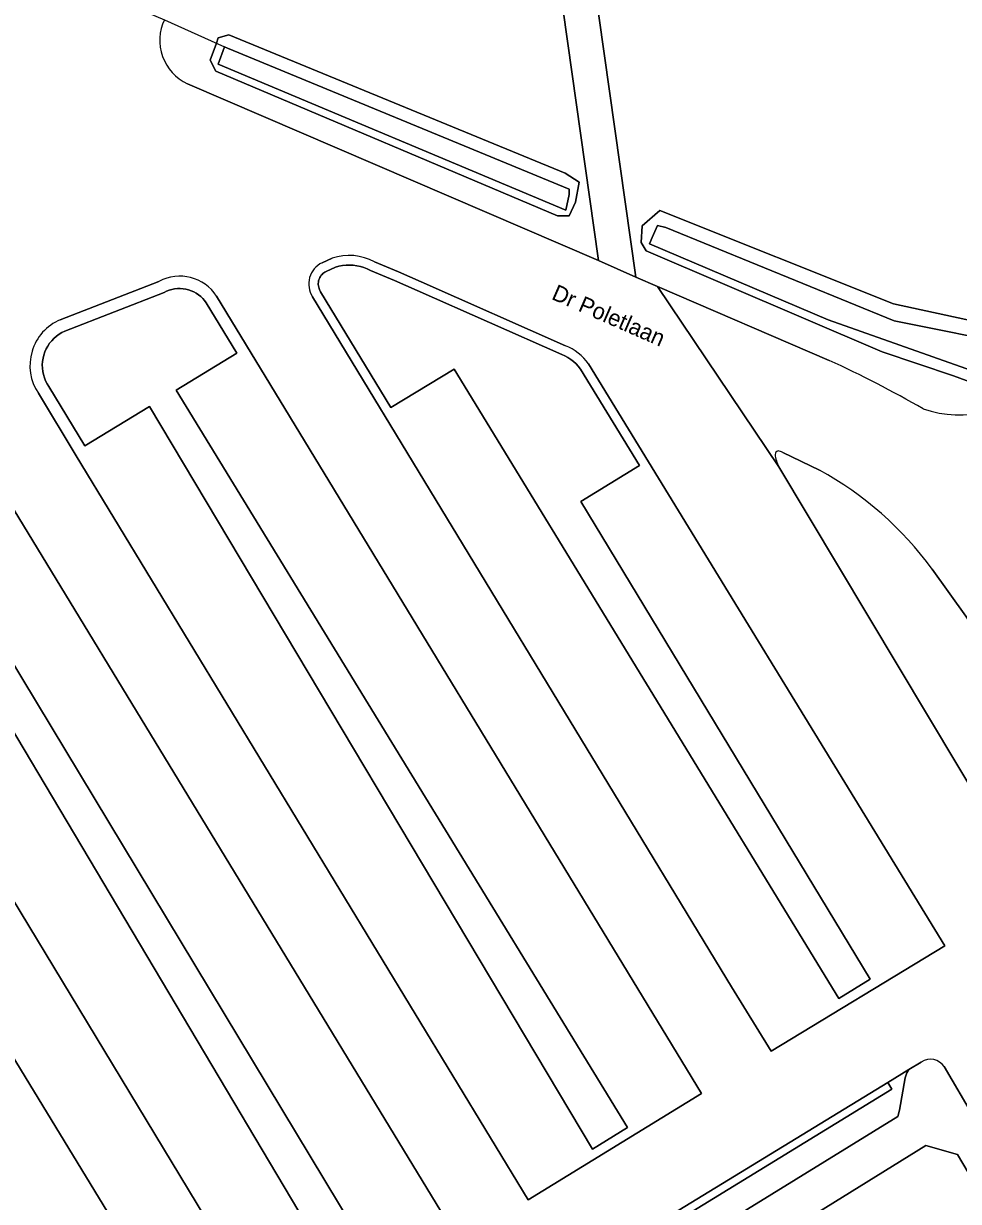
# Model space of a CAD drawing. Extents: x 158132 to 159664, y 385256 to 387218.
# Drawn here: x 158617.8 to 158675.2, y 386803.8 to 386876.1 of the extents above; entities that cross this region are included whole.
import ezdxf

# ---------------------------------------------------------------- set-up
doc = ezdxf.new("R2010")
doc.units = 0
for name, color, linetype in [('IMGEO_Duiker', 7, 'Continuous'), ('IMGEO_Gemengd_bos', 7, 'Continuous'), ('IMGEO_Groenvoorziening', 7, 'Continuous'), ('IMGEO_Oever', 7, 'Continuous'), ('IMGEO_Openbare_ruimte_label', 7, 'Continuous'), ('IMGEO_Parkeervlak_open', 7, 'Continuous'), ('IMGEO_Rijbaan_lokaal_gesloten', 7, 'Continuous'), ('IMGEO_Rijbaan_lokaal_open', 7, 'Continuous'), ('IMGEO_Voetpad_gesloten', 7, 'Continuous'), ('IMGEO_Voetpad_open', 7, 'Continuous'), ('IMGEO_Waterloop', 7, 'Continuous')]:
    doc.layers.add(name, color=color, linetype=linetype)

msp = doc.modelspace()

# ---------------------------------------------------------------- linework, layer by layer
at = {"layer": 'IMGEO_Duiker'}
msp.add_lwpolyline([(158619.115, 386879.444), (158619.244, 386879.388), (158620.829, 386878.697), (158626.462, 386876.298), (158630.151, 386874.635), (158630.327, 386874.558)], dxfattribs=at)
at = {"layer": 'IMGEO_Gemengd_bos'}
msp.add_lwpolyline([(158687.811, 387060.409), (158689.817, 387061.157), (158703.822, 387101.712), (158681.036, 387088.113), (158663.513, 387076.566), (158660.407, 387074.962), (158660.01, 387075.699), (158644.038, 387067.333), (158614.63, 387050.481), (158601.872, 387043.698), (158647.808, 386955.65), (158659.443, 386961.72), (158679.256, 386924.451), (158648.608, 386908.461), (158655.384, 386860.517), (158656.73, 386859.937), (158667.25, 386855.404)], dxfattribs=at)
msp.add_lwpolyline([(158656.867, 386864.6), (158671.198, 386858.872), (158680.086, 386856.956), (158679.662, 386854.103), (158679.075, 386853.884), (158677.759, 386853.393), (158674.889, 386854.448), (158670.513, 386855.935), (158656.017, 386862.127), (158655.715, 386862.635), (158655.771, 386863.651)], close=True, dxfattribs=at)
for centre, radius, start, end in [((158638.753, 386793.042), 68.565, 60.00896, 65.44143), ((158675.246, 386859.022), 6.959, 251.40123, 316.75632)]:
    msp.add_arc(centre, radius, start, end, dxfattribs=at)
at = {"layer": 'IMGEO_Groenvoorziening'}
for points in [[(158627.875, 386872.369), (158630.221, 386871.36), (158653.095, 386861.525), (158646.576, 386907.685)], [(158666.67, 386848.674), (158664.408, 386849.76)], [(158664.173, 386848.883), (158678.814, 386824.435)], [(158639.846, 386799.251), (158611.508, 386846.181)], [(158681.302, 386830.498), (158677.109, 386837.457), (158675.65, 386839.708), (158673.58, 386842.598)], [(158612.053, 386841.27), (158637.792, 386798.011)], [(158679.268, 386799.741), (158675.134, 386806.696), (158673.193, 386807.258), (158661.926, 386800.289), (158662.412, 386799.415), (158661.038, 386798.599), (158660.541, 386799.433), (158660.438, 386799.369), (158658.36, 386798.138), (158645.464, 386790.273), (158643.388, 386789.021), (158630.554, 386781.129), (158628.471, 386779.831), (158615.58, 386772.037), (158613.511, 386770.8), (158602.495, 386764.073), (158600.165, 386764.485), (158598.81, 386764.724), (158595.398, 386758.151), (158598.248, 386753.226), (158595.064, 386751.272), (158577.065, 386740.009)]]:
    msp.add_lwpolyline(points, dxfattribs=at)
for points in [[(158651.055, 386866.893), (158651.904, 386866.336), (158651.692, 386865.112), (158651.303, 386864.276), (158650.589, 386864.276), (158629.61, 386873.148), (158629.277, 386873.812), (158629.654, 386874.859), (158629.769, 386875.176), (158630.416, 386875.365)], [(158655.619, 386848.952), (158651.99, 386854.875), (158651.861, 386855.04), (158651.719, 386855.194), (158651.564, 386855.335), (158651.399, 386855.464), (158651.223, 386855.579), (158651.039, 386855.679), (158650.847, 386855.764), (158641.978, 386859.686), (158640.591, 386860.3), (158639.1, 386860.91), (158638.904, 386861.011), (158638.699, 386861.095), (158638.488, 386861.162), (158638.272, 386861.21), (158638.053, 386861.241), (158637.832, 386861.253), (158637.611, 386861.246), (158637.392, 386861.221), (158637.175, 386861.178), (158636.962, 386861.117), (158636.381, 386860.861), (158636.314, 386860.824), (158636.251, 386860.781), (158636.192, 386860.732), (158636.137, 386860.678), (158636.087, 386860.62), (158636.043, 386860.557), (158636.005, 386860.491), (158635.972, 386860.422), (158635.946, 386860.35), (158635.926, 386860.276), (158635.913, 386860.201), (158635.907, 386860.124), (158635.907, 386860.048), (158635.914, 386859.971), (158635.928, 386859.896), (158635.949, 386859.822), (158635.976, 386859.751), (158636.009, 386859.682), (158636.049, 386859.616), (158640.363, 386852.514), (158644.245, 386854.872), (158667.842, 386816.275), (158669.778, 386817.448), (158652.015, 386846.744)], [(158654.874, 386808.351), (158627.174, 386853.568), (158630.909, 386855.841), (158629.026, 386858.935), (158628.925, 386859.074), (158628.813, 386859.204), (158628.689, 386859.323), (158628.555, 386859.431), (158628.413, 386859.527), (158628.262, 386859.609), (158628.105, 386859.679), (158627.942, 386859.734), (158627.775, 386859.774), (158627.605, 386859.8), (158627.434, 386859.811), (158627.262, 386859.806), (158627.091, 386859.786), (158626.923, 386859.752), (158626.759, 386859.702), (158626.599, 386859.639), (158626.446, 386859.561), (158620.361, 386857.198), (158620.178, 386857.11), (158620.004, 386857.007), (158619.84, 386856.888), (158619.687, 386856.756), (158619.546, 386856.61), (158619.418, 386856.453), (158619.305, 386856.285), (158619.208, 386856.107), (158619.126, 386855.922), (158619.061, 386855.73), (158619.013, 386855.534), (158618.982, 386855.333), (158618.97, 386855.131), (158618.975, 386854.929), (158618.998, 386854.728), (158619.039, 386854.529), (158619.097, 386854.335), (158619.172, 386854.147), (158619.264, 386853.967), (158619.371, 386853.795), (158621.577, 386850.166), (158625.552, 386852.581), (158652.735, 386807.04)], [(158672.143, 386811.908), (158670.853, 386811.121), (158671.1, 386810.713), (158658.248, 386802.847), (158656.171, 386801.575), (158643.345, 386793.726), (158641.261, 386792.449), (158628.427, 386784.594), (158626.326, 386783.308), (158613.495, 386775.456), (158611.401, 386774.174), (158600.138, 386767.28), (158600.031, 386767.075), (158602.159, 386766.707), (158631.575, 386784.467), (158671.459, 386809.025), (158671.568, 386809.413), (158671.926, 386811.406), (158672.029, 386811.721)]]:
    msp.add_lwpolyline(points, close=True, dxfattribs=at)
for centre, radius, start, end in [((158629.124, 386875.037), 2.945, 154.6443, 244.91627), ((158664.173, 386849.627), 0.235, 104.46981, 177.44194), ((158663.805, 386848.379), 1.507, 66.39008, 78.14887), ((158665.708, 386849.775), 1.775, 184.46014, 210.16136), ((158656.337, 386829.956), 21.381, 36.24859, 61.10073)]:
    msp.add_arc(centre, radius, start, end, dxfattribs=at)
at = {"layer": 'IMGEO_Oever'}
for points in [[(158651.055, 386866.893), (158630.416, 386875.365), (158629.769, 386875.176), (158629.654, 386874.859), (158629.277, 386873.812), (158629.61, 386873.148), (158650.589, 386864.276), (158651.303, 386864.276), (158651.692, 386865.112), (158651.904, 386866.336)], [(158630.151, 386874.635), (158630.327, 386874.558), (158651.303, 386865.909), (158651.303, 386865.576), (158651.096, 386864.608), (158629.766, 386873.576)], [(158656.867, 386864.6), (158655.771, 386863.651), (158655.715, 386862.635), (158656.017, 386862.127), (158670.513, 386855.935), (158674.889, 386854.448), (158677.759, 386853.393), (158679.075, 386853.884), (158679.662, 386854.103), (158680.086, 386856.956), (158671.198, 386858.872)], [(158657.221, 386863.55), (158671.234, 386857.838), (158678.998, 386856.266), (158678.998, 386854.77), (158678.671, 386854.535), (158678.008, 386854.06), (158667.187, 386857.887), (158656.239, 386862.56), (158656.397, 386862.932), (158656.715, 386863.682)]]:
    msp.add_lwpolyline(points, close=True, dxfattribs=at)
at = {"layer": 'IMGEO_Parkeervlak_open'}
for points in [[(158636.75, 386861.663), (158636.133, 386861.392)], [(158651.073, 386856.304), (158642.215, 386860.222), (158640.82, 386860.839), (158639.355, 386861.439)], [(158626.125, 386860.251), (158620.075, 386857.901)], [(158618.732, 386853.384), (158621.057, 386849.56), (158648.785, 386803.923), (158659.417, 386810.444), (158629.668, 386859.34)], [(158635.553, 386859.304), (158661.265, 386816.98), (158663.691, 386813.049), (158674.348, 386819.505), (158652.479, 386855.198)], [(158606.261, 386840.323), (158631.543, 386798.594), (158633.83, 386794.789), (158644.565, 386801.344), (158615.215, 386849.516)], [(158611.508, 386846.181), (158639.846, 386799.251)], [(158637.792, 386798.011), (158612.053, 386841.27)], [(158596.366, 386822.775), (158600.816, 386815.432), (158618.919, 386785.65), (158629.653, 386792.202), (158606.165, 386830.714)]]:
    msp.add_lwpolyline(points, dxfattribs=at)
for points in [[(158655.619, 386848.952), (158652.015, 386846.744), (158669.778, 386817.448), (158667.842, 386816.275), (158644.245, 386854.872), (158640.363, 386852.514), (158636.049, 386859.616), (158636.009, 386859.682), (158635.976, 386859.751), (158635.949, 386859.822), (158635.928, 386859.896), (158635.914, 386859.971), (158635.907, 386860.048), (158635.907, 386860.124), (158635.913, 386860.201), (158635.926, 386860.276), (158635.946, 386860.35), (158635.972, 386860.422), (158636.005, 386860.491), (158636.043, 386860.557), (158636.087, 386860.62), (158636.137, 386860.678), (158636.192, 386860.732), (158636.251, 386860.781), (158636.314, 386860.824), (158636.381, 386860.861), (158636.962, 386861.117), (158637.175, 386861.178), (158637.392, 386861.221), (158637.611, 386861.246), (158637.832, 386861.253), (158638.053, 386861.241), (158638.272, 386861.21), (158638.488, 386861.162), (158638.699, 386861.095), (158638.904, 386861.011), (158639.1, 386860.91), (158640.591, 386860.3), (158641.978, 386859.686), (158650.847, 386855.764), (158651.039, 386855.679), (158651.223, 386855.579), (158651.399, 386855.464), (158651.564, 386855.335), (158651.719, 386855.194), (158651.861, 386855.04), (158651.99, 386854.875)], [(158654.874, 386808.351), (158652.735, 386807.04), (158625.552, 386852.581), (158621.577, 386850.166), (158619.371, 386853.795), (158619.264, 386853.967), (158619.172, 386854.147), (158619.097, 386854.335), (158619.039, 386854.529), (158618.998, 386854.728), (158618.975, 386854.929), (158618.97, 386855.131), (158618.982, 386855.333), (158619.013, 386855.534), (158619.061, 386855.73), (158619.126, 386855.922), (158619.208, 386856.107), (158619.305, 386856.285), (158619.418, 386856.453), (158619.546, 386856.61), (158619.687, 386856.756), (158619.84, 386856.888), (158620.004, 386857.007), (158620.178, 386857.11), (158620.361, 386857.198), (158626.446, 386859.561), (158626.599, 386859.639), (158626.759, 386859.702), (158626.923, 386859.752), (158627.091, 386859.786), (158627.262, 386859.806), (158627.434, 386859.811), (158627.605, 386859.8), (158627.775, 386859.774), (158627.942, 386859.734), (158628.105, 386859.679), (158628.262, 386859.609), (158628.413, 386859.527), (158628.555, 386859.431), (158628.689, 386859.323), (158628.813, 386859.204), (158628.925, 386859.074), (158629.026, 386858.935), (158630.909, 386855.841), (158627.174, 386853.568)]]:
    msp.add_lwpolyline(points, close=True, dxfattribs=at)
for centre, radius, start, end in [((158636.768, 386860.091), 1.448, 116.0276, 212.92417), ((158637.8, 386858.613), 3.226, 61.17694, 108.99369), ((158627.399, 386857.863), 2.707, 33.07636, 118.08383), ((158621.262, 386855.09), 3.051, 112.88922, 213.99411), ((158649.909, 386853.377), 3.15, 35.31471, 68.30608)]:
    msp.add_arc(centre, radius, start, end, dxfattribs=at)
at = {"layer": 'IMGEO_Rijbaan_lokaal_gesloten'}
for points in [[(158678.814, 386824.435), (158664.173, 386848.883), (158656.73, 386859.937), (158655.384, 386860.517), (158653.095, 386861.525), (158630.221, 386871.36), (158627.875, 386872.369)], [(158636.133, 386861.392), (158636.75, 386861.663)], [(158639.355, 386861.439), (158640.82, 386860.839), (158642.215, 386860.222), (158651.073, 386856.304)], [(158620.075, 386857.901), (158626.125, 386860.251)], [(158667.25, 386855.404), (158656.73, 386859.937), (158664.173, 386848.883)], [(158629.668, 386859.34), (158659.417, 386810.444)], [(158663.691, 386813.049), (158661.265, 386816.98), (158635.553, 386859.304)], [(158652.479, 386855.198), (158674.348, 386819.505), (158663.691, 386813.049)], [(158659.417, 386810.444), (158648.785, 386803.923), (158621.057, 386849.56), (158618.732, 386853.384)], [(158615.215, 386849.516), (158644.565, 386801.344)], [(158664.408, 386849.76), (158666.67, 386848.674)], [(158673.58, 386842.598), (158675.65, 386839.708), (158677.109, 386837.457), (158681.302, 386830.498), (158691.175, 386815.605), (158691.175, 386815.499), (158695.421, 386808.652), (158696.429, 386807.026), (158711.194, 386783.216), (158718.254, 386772.673), (158718.278, 386772.645), (158718.299, 386772.615), (158718.318, 386772.584), (158718.333, 386772.55), (158718.346, 386772.516), (158718.486, 386772.282), (158720.989, 386768.104), (158725.879, 386760.147), (158726.585, 386759.37), (158727.175, 386758.581), (158732.496, 386750), (158738.155, 386740.875)], [(158644.565, 386801.344), (158633.83, 386794.789), (158631.543, 386798.594), (158606.261, 386840.323)], [(158606.165, 386830.714), (158629.653, 386792.202), (158618.919, 386785.65)], [(158592.353, 386820.083), (158614.738, 386783.091), (158608.242, 386779.1), (158607.927, 386779.616), (158593.624, 386803.05), (158591.414, 386801.743), (158583.798, 386814.628), (158580.834, 386812.851), (158588.566, 386799.981), (158599.018, 386782.777), (158603.042, 386776.127), (158597.618, 386772.831), (158600.643, 386768.254), (158612.342, 386775.397), (158670.853, 386811.121), (158672.143, 386811.908), (158672.903, 386812.372)], [(158674.32, 386812.091), (158676.141, 386809)]]:
    msp.add_lwpolyline(points, dxfattribs=at)
for centre, radius, start, end in [((158629.124, 386875.037), 2.945, 154.6443, 244.91627), ((158636.768, 386860.091), 1.448, 116.0276, 212.92417), ((158637.8, 386858.613), 3.226, 61.17694, 108.99369), ((158627.399, 386857.863), 2.707, 33.07636, 118.08383), ((158621.262, 386855.09), 3.051, 112.88922, 213.99411), ((158649.909, 386853.377), 3.15, 35.31471, 68.30608), ((158638.753, 386793.042), 68.565, 60.00896, 65.44143), ((158675.246, 386859.022), 6.959, 251.40123, 316.75632), ((158664.173, 386849.627), 0.235, 104.46981, 177.44194), ((158663.805, 386848.379), 1.507, 66.39008, 78.14887), ((158665.708, 386849.775), 1.775, 184.46014, 210.16136), ((158656.337, 386829.956), 21.381, 36.24859, 61.10073), ((158673.468, 386811.509), 1.031, 34.33021, 123.2366)]:
    msp.add_arc(centre, radius, start, end, dxfattribs=at)
at = {"layer": 'IMGEO_Rijbaan_lokaal_open'}
msp.add_lwpolyline([(158641.261, 386792.449), (158643.345, 386793.726), (158656.171, 386801.575), (158658.248, 386802.847), (158671.1, 386810.713), (158670.853, 386811.121), (158612.342, 386775.397), (158600.643, 386768.254), (158600.138, 386767.28), (158611.401, 386774.174), (158613.495, 386775.456), (158626.326, 386783.308), (158628.427, 386784.594)], close=True, dxfattribs=at)
at = {"layer": 'IMGEO_Voetpad_gesloten'}
msp.add_lwpolyline([(158646.576, 386907.685), (158653.095, 386861.525), (158655.384, 386860.517), (158648.608, 386908.461)], dxfattribs=at)
at = {"layer": 'IMGEO_Voetpad_open'}
for points in [[(158672.903, 386812.372), (158672.143, 386811.908), (158672.029, 386811.721), (158671.926, 386811.406), (158671.568, 386809.413), (158671.459, 386809.025), (158631.575, 386784.467), (158602.159, 386766.707), (158600.031, 386767.075), (158599.357, 386765.777), (158598.81, 386764.724), (158600.165, 386764.485), (158602.495, 386764.073), (158613.511, 386770.8), (158615.58, 386772.037), (158628.471, 386779.831), (158630.554, 386781.129)], [(158676.141, 386809), (158674.32, 386812.091)], [(158630.554, 386781.129), (158643.388, 386789.021), (158645.464, 386790.273), (158658.36, 386798.138), (158660.438, 386799.369), (158660.541, 386799.433), (158661.926, 386800.289), (158673.193, 386807.258), (158675.134, 386806.696), (158679.268, 386799.741)]]:
    msp.add_lwpolyline(points, dxfattribs=at)
msp.add_arc((158673.468, 386811.509), 1.031, 34.33021, 123.2366, dxfattribs=at)
at = {"layer": 'IMGEO_Waterloop'}
for points in [[(158630.151, 386874.635), (158629.766, 386873.576), (158651.096, 386864.608), (158651.303, 386865.576), (158651.303, 386865.909), (158630.327, 386874.558)], [(158657.221, 386863.55), (158656.715, 386863.682), (158656.397, 386862.932), (158656.239, 386862.56), (158667.187, 386857.887), (158678.008, 386854.06), (158678.671, 386854.535), (158678.998, 386854.77), (158678.998, 386856.266), (158671.234, 386857.838)]]:
    msp.add_lwpolyline(points, close=True, dxfattribs=at)

# ---------------------------------------------------------------- texts
at = {"layer": 'IMGEO_Openbare_ruimte_label'}
msp.add_text('Dr Poletlaan', height=1, rotation=336.3575, dxfattribs=at).set_placement((158650.159, 386859.182))

doc.saveas('drawing.dxf')
